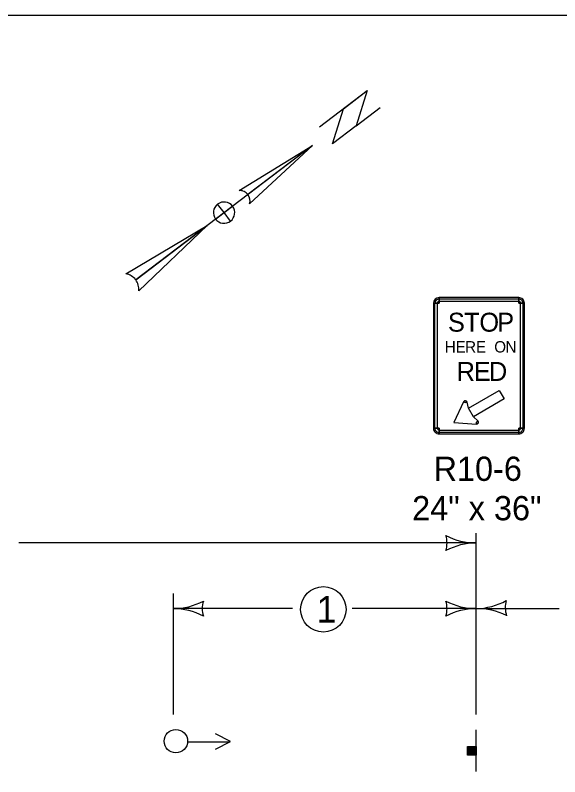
# Model space of a CAD drawing. Extents: x -2134934 to -2119606, y -2139046 to -2137036.
# Drawn here: x -2128116 to -2127757, y -2137539 to -2137036 of the extents above; entities that cross this region are included whole.
import ezdxf

# ---------------------------------------------------------------- set-up
doc = ezdxf.new("R2010")
doc.units = 0
for name, color, linetype in [('Default', 7, 'Continuous'), ('dsnCellElements', 7, 'Continuous'), ('dsnCellsScaleBlock', 7, 'Continuous'), ('dsnStdLabel', 7, 'Continuous'), ('Level 2', 7, 'Continuous')]:
    doc.layers.add(name, color=color, linetype=linetype)

msp = doc.modelspace()

# ---------------------------------------------------------------- linework, layer by layer
at = {"layer": 'Default'}
msp.add_lwpolyline([(-2130231.95, -2137035.95), (-2127096.96, -2137035.95), (-2127096.96, -2139045.94), (-2130231.95, -2139045.94)], close=True, dxfattribs=at)
at = {"layer": 'dsnCellElements'}
for centre, radius, start, end in [((-2127847.59, -2137384.37), 16.42, 342.2666, 17.7334), ((-2127811.95, -2137341.87), 42.5, 241.9275, 270), ((-2127811.95, -2137426.87), 42.5, 90, 118.0725)]:
    msp.add_arc(centre, radius, start, end, dxfattribs=at)
at = {"layer": 'dsnCellsScaleBlock'}
for p, q in [((-2127919.98, -2137121.99), (-2128036.64, -2137210.58)), ((-2127919.98, -2137121.99), (-2127961.44, -2137160.55)), ((-2127968.25, -2137151.58), (-2127968.25, -2137151.57)), ((-2127967.71, -2137151.43), (-2127966.14, -2137151.56)), ((-2127983.92, -2137170.54), (-2127983.92, -2137170.54)), ((-2128043.14, -2137206.68), (-2127989.53, -2137174.8))]:
    msp.add_line(p, q, dxfattribs=at)
for points in [[(-2127915.26, -2137109.56), (-2127883.85, -2137085.71), (-2127891.04, -2137108.86), (-2127875.33, -2137096.93)], [(-2127968.25, -2137151.57), (-2127919.98, -2137121.99), (-2127962.6, -2137154.36)], [(-2127983.92, -2137170.54), (-2127978.31, -2137166.28), (-2127982.57, -2137160.67)], [(-2127974.05, -2137171.89), (-2127978.31, -2137166.28), (-2127972.7, -2137162.02)], [(-2128036.64, -2137210.58), (-2127989.53, -2137174.8), (-2128034.62, -2137217.89)]]:
    msp.add_lwpolyline(points, dxfattribs=at)
msp.add_lwpolyline([(-2127906.74, -2137120.78), (-2127899.56, -2137097.64), (-2127883.85, -2137085.71), (-2127891.04, -2137108.86)], close=True, dxfattribs=at)
for centre, radius, start, end in [((-2127968.21, -2137158.62), 7.04, 37.2325, 90.3379), ((-2127968.21, -2137158.62), 7.04, 344.0602, 37.234), ((-2127978.31, -2137166.28), 7.04, 127.2121, 217.2121), ((-2127978.31, -2137166.28), 7.04, 37.2121, 127.2121), ((-2127978.31, -2137166.28), 7.04, 307.2121, 37.2121), ((-2127978.31, -2137166.28), 7.04, 217.2121, 307.2121), ((-2128044.77, -2137216.75), 10.2, 37.2015, 80.8311), ((-2128044.77, -2137216.76), 10.21, 353.6142, 37.2128)]:
    msp.add_arc(centre, radius, start, end, dxfattribs=at)
at = {"layer": 'dsnStdLabel'}
for p, q in [((-2127840.12, -2137226.09), (-2127836.37, -2137226.09)), ((-2127839.18, -2137226.09), (-2127837.62, -2137226.09)), ((-2127836.37, -2137226.09), (-2127836.37, -2137222.34)), ((-2127836.37, -2137224.84), (-2127836.37, -2137223.27)), ((-2127783.87, -2137222.34), (-2127783.87, -2137226.09)), ((-2127783.87, -2137223.27), (-2127783.87, -2137224.84)), ((-2127783.87, -2137226.09), (-2127780.12, -2137226.09)), ((-2127782.62, -2137226.09), (-2127781.06, -2137226.09)), ((-2127820.26, -2137291.07), (-2127819.15, -2137291.65)), ((-2127819.15, -2137291.65), (-2127817.93, -2137291.38)), ((-2127811.65, -2137304.64), (-2127811.7, -2137305.89)), ((-2127810.81, -2137303.72), (-2127811.65, -2137304.64)), ((-2127836.37, -2137308.59), (-2127840.12, -2137308.59)), ((-2127837.62, -2137308.59), (-2127839.18, -2137308.59)), ((-2127836.37, -2137312.34), (-2127836.37, -2137308.59)), ((-2127836.37, -2137311.4), (-2127836.37, -2137309.84)), ((-2127780.12, -2137308.59), (-2127783.87, -2137308.59)), ((-2127783.87, -2137308.59), (-2127783.87, -2137312.34)), ((-2127783.87, -2137309.84), (-2127783.87, -2137311.4)), ((-2127781.06, -2137308.59), (-2127782.62, -2137308.59))]:
    msp.add_line(p, q, dxfattribs=at)
for points in [[(-2127836.37, -2137312.34), (-2127783.87, -2137312.34), (-2127783.87, -2137308.59), (-2127780.12, -2137308.59), (-2127780.12, -2137226.09), (-2127783.87, -2137226.09), (-2127783.87, -2137222.34), (-2127836.37, -2137222.34), (-2127836.37, -2137226.09), (-2127840.12, -2137226.09), (-2127840.12, -2137308.59), (-2127836.37, -2137308.59), (-2127836.37, -2137312.34)], [(-2127837.62, -2137226.09), (-2127837.62, -2137308.59), (-2127839.18, -2137308.59), (-2127839.18, -2137226.09), (-2127837.62, -2137226.09)], [(-2127783.87, -2137224.84), (-2127836.37, -2137224.84), (-2127836.37, -2137223.27), (-2127783.87, -2137223.27), (-2127783.87, -2137224.84)], [(-2127782.62, -2137308.59), (-2127782.62, -2137226.09), (-2127781.06, -2137226.09), (-2127781.06, -2137308.59), (-2127782.62, -2137308.59)], [(-2127796.75, -2137283.59), (-2127793.47, -2137289.27), (-2127813.77, -2137300.99), (-2127817.05, -2137295.31), (-2127796.75, -2137283.59)], [(-2127826.77, -2137304.71), (-2127811.7, -2137305.89), (-2127811.65, -2137304.64), (-2127810.81, -2137303.72), (-2127813.77, -2137300.99), (-2127817.05, -2137295.31), (-2127817.93, -2137291.38), (-2127819.15, -2137291.65), (-2127820.26, -2137291.07), (-2127826.77, -2137304.71)], [(-2127836.37, -2137309.84), (-2127783.87, -2137309.84), (-2127783.87, -2137311.4), (-2127836.37, -2137311.4), (-2127836.37, -2137309.84)]]:
    msp.add_lwpolyline(points, close=True, dxfattribs=at)
for centre, radius, start, end in [((-2127836.37, -2137226.09), 3.75, 90.0002, 179.9998), ((-2127836.37, -2137226.09), 2.81, 90.0002, 179.9998), ((-2127836.37, -2137226.09), 1.25, 90.0002, 179.9998), ((-2127783.87, -2137226.09), 3.75, 0, 90.0002), ((-2127783.87, -2137226.09), 2.81, 0, 90.0002), ((-2127783.87, -2137226.09), 1.25, 0, 90.0002), ((-2127819.15, -2137291.65), 1.25, 12.6223, 152.2756), ((-2127811.65, -2137304.64), 1.25, 267.7243, 47.3776), ((-2127836.37, -2137308.59), 3.75, 179.9998, 270.0001), ((-2127836.37, -2137308.59), 2.81, 179.9998, 270.0001), ((-2127836.37, -2137308.59), 1.25, 179.9998, 270.0001), ((-2127783.87, -2137308.59), 3.75, 270.0001, 0.0003), ((-2127783.87, -2137308.59), 2.81, 270.0001, 0.0003), ((-2127783.87, -2137308.59), 1.25, 270.0001, 0.0003)]:
    msp.add_arc(centre, radius, start, end, dxfattribs=at)
at = {"layer": 'Level 2'}
for p, q in [((-2127811.95, -2137497.66), (-2127811.95, -2137377.91)), ((-2127811.95, -2137384.33), (-2128113.68, -2137384.33)), ((-2128011.93, -2137417.66), (-2128011.93, -2137497.66)), ((-2127933.15, -2137427.66), (-2128011.93, -2137427.66)), ((-2127811.93, -2137427.66), (-2127893.7, -2137427.66)), ((-2127811.95, -2137427.66), (-2127757.21, -2137427.66)), ((-2127811.95, -2137535.16), (-2127811.95, -2137507.66)), ((-2128002.38, -2137515.52), (-2127974.44, -2137515.52)), ((-2127817.28, -2137524.3), (-2127817.28, -2137518.71)), ((-2127816.96, -2137518.71), (-2127816.96, -2137524.3)), ((-2127816.74, -2137524.3), (-2127816.74, -2137518.71)), ((-2127816.42, -2137518.71), (-2127816.42, -2137524.3)), ((-2127816.19, -2137524.3), (-2127816.21, -2137518.71)), ((-2127815.78, -2137518.71), (-2127815.76, -2137524.3)), ((-2127815.56, -2137524.3), (-2127815.56, -2137518.71)), ((-2127815.12, -2137518.71), (-2127815.12, -2137524.3)), ((-2127814.75, -2137524.3), (-2127814.75, -2137518.71)), ((-2127814.43, -2137518.71), (-2127814.41, -2137524.3)), ((-2127814.21, -2137524.3), (-2127814.21, -2137518.71)), ((-2127813.94, -2137518.71), (-2127813.94, -2137524.3)), ((-2127813.61, -2137524.3), (-2127813.61, -2137518.71)), ((-2127813.4, -2137518.71), (-2127813.4, -2137524.3)), ((-2127813.17, -2137524.3), (-2127813.17, -2137518.71)), ((-2127812.91, -2137518.71), (-2127812.91, -2137524.3)), ((-2127812.65, -2137524.3), (-2127812.65, -2137518.71)), ((-2127812.37, -2137518.71), (-2127812.37, -2137524.3))]:
    msp.add_line(p, q, dxfattribs=at)
msp.add_lwpolyline([(-2127984.07, -2137520.34), (-2127974.07, -2137515.34), (-2127984.07, -2137510.34)], dxfattribs=at)
msp.add_lwpolyline([(-2127812.05, -2137518.71), (-2127812.05, -2137524.34), (-2127817.67, -2137524.34), (-2127817.67, -2137518.71)], close=True, dxfattribs=at)
for centre, radius in [((-2127912.79, -2137428.16), 15), ((-2128010.12, -2137515.16), 7.74)]:
    msp.add_circle(centre, radius, dxfattribs=at)
for centre, radius, start, end in [((-2128011.93, -2137385.16), 42.5, 270, 298.0725), ((-2127976.3, -2137427.66), 16.42, 162.2666, 197.7334), ((-2127847.57, -2137427.66), 16.42, 342.2666, 17.7334), ((-2127811.93, -2137385.16), 42.5, 241.9275, 270), ((-2127812.71, -2137385.17), 42.5, 271.0176, 299.0725), ((-2127776.34, -2137427.04), 16.42, 163.2666, 198.7334), ((-2128011.93, -2137470.16), 42.5, 61.9275, 90), ((-2127811.93, -2137470.16), 42.5, 90, 118.0725), ((-2127811.23, -2137470.15), 42.5, 62.9275, 90.9824)]:
    msp.add_arc(centre, radius, start, end, dxfattribs=at)

# ---------------------------------------------------------------- texts
at = {"layer": 'dsnStdLabel'}
for s, height, p in [('S', 12.5, (-2127830.57, -2137244.84)), ('T', 12.5, (-2127819.8, -2137244.84)), ('O', 12.5, (-2127809.82, -2137244.84)), ('P', 12.5, (-2127798.07, -2137244.84)), ('H', 7.5, (-2127832.64, -2137258.59)), ('E', 7.5, (-2127825.49, -2137258.59)), ('R', 7.5, (-2127819.24, -2137258.59)), ('E', 7.5, (-2127812.09, -2137258.59)), ('O', 7.5, (-2127800.02, -2137258.59)), ('N', 7.5, (-2127792.63, -2137258.59)), ('R', 12.5, (-2127824.81, -2137277.34)), ('E', 12.5, (-2127813.48, -2137277.34)), ('D', 12.5, (-2127803.52, -2137277.34)), ('R10-6', 16, (-2127840.05, -2137343.34)), ('24" x 36"', 16, (-2127854.19, -2137369.34))]:
    msp.add_text(s, height=height, dxfattribs=at).set_placement(p)
at = {"layer": 'Level 2'}
msp.add_text('1', height=17.5, dxfattribs=at).set_placement((-2127917.25, -2137436.91))

doc.saveas('drawing.dxf')
